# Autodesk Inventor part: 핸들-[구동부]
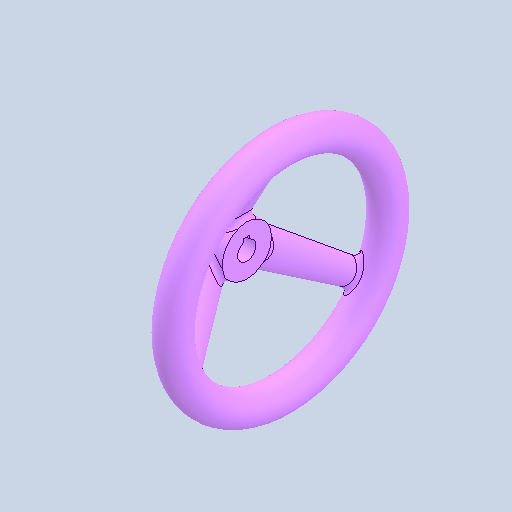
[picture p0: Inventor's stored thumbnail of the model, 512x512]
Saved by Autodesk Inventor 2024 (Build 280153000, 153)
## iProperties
Created: 2024-08
Part Number: 핸들-[구동부]
Material: 일반
Document SubType Name: Modeling
Designer: user
Density: 1 g/cm^3
Appearance: 기본값
Sending System: Autodesk Inventor 2025
Preprocessor: ST-DEVELOPER v20
Author: jhkim
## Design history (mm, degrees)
feature "솔리드1"
node "솔리드2"
